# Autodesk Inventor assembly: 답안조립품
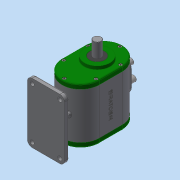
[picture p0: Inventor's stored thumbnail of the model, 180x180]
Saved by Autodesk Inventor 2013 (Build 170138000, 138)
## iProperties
Created: 2018-10
Part Number: 답안조립품
Document SubType Name: Assembly
Designer: Administrator
Author: Administrator
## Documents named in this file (15)
- C:\Users\Administrator\Desktop\381007V1029\답안조립품.iam
- C:\Users\Administrator\Desktop\381007V1029\본체.ipt
- C:\Users\Administrator\Desktop\381007V1029\뒤커버.ipt
- C:\Users\Administrator\Desktop\381007V1029\메인축.ipt
- C:\Users\Administrator\Desktop\381007V1029\베어링 608.ipt
- C:\Users\Administrator\Desktop\381007V1029\베어링 6003.ipt
- C:\Users\Administrator\Desktop\381007V1029\볼트 M4.ipt
- C:\Users\Administrator\Desktop\381007V1029\부시.ipt
- C:\Users\Administrator\Desktop\381007V1029\서브축.ipt
- C:\Users\Administrator\Desktop\381007V1029\슬라이더.ipt
- C:\Users\Administrator\Desktop\381007V1029\앞커버.ipt
- C:\Users\Administrator\Desktop\381007V1029\오일실 8 22 7.ipt
- C:\Users\Administrator\Desktop\381007V1029\오일실 17 32 8.ipt
- C:\Users\Administrator\Desktop\381007V1029\가변스프링1.ipt
- C:\Users\Administrator\Desktop\381007V1029\가변스프링2.ipt
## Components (2 placed, 2 different names)
1. 가변스프링1:1
2. 가변스프링2:1
